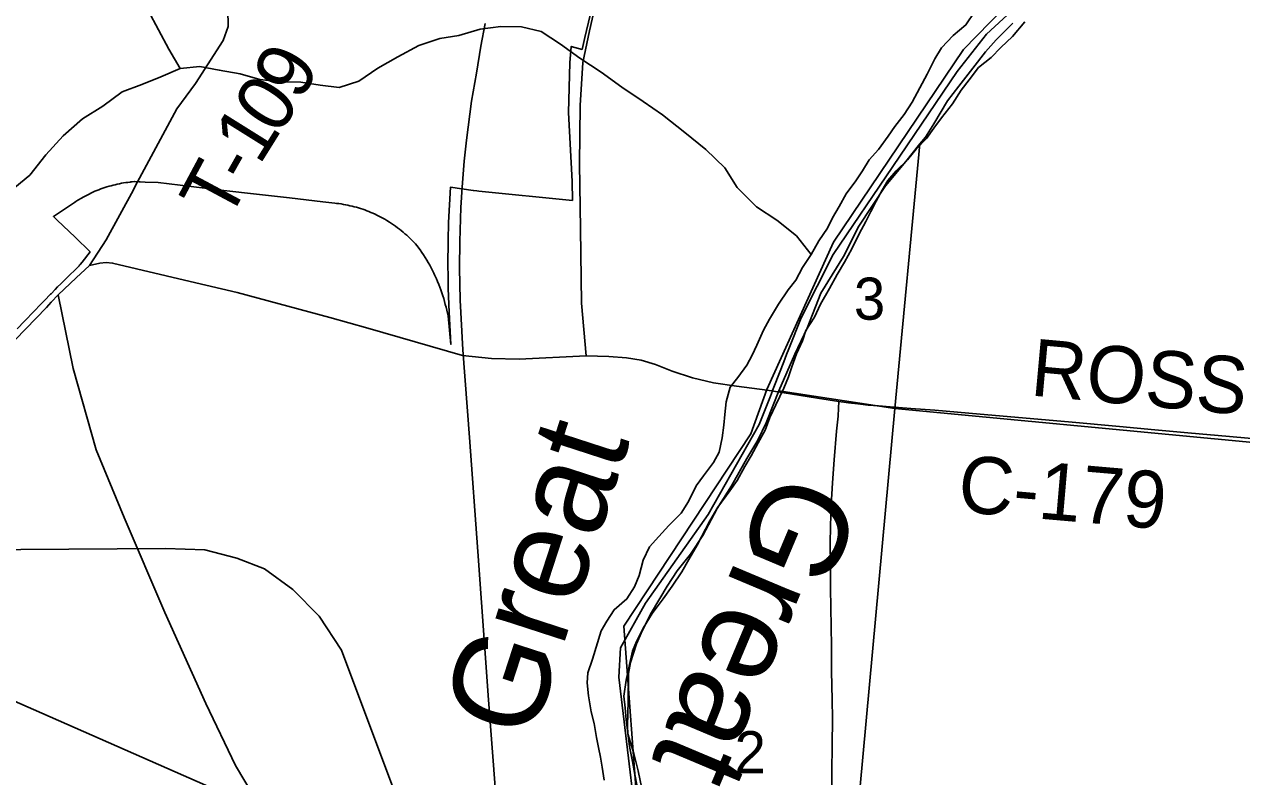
# Model space of a CAD drawing. Extents: x -38.1 to 35.9, y -2.7 to 28.5.
# Drawn here: x 9.309 to 10.521, y 16.967 to 17.716 of the extents above; entities that cross this region are included whole.
import ezdxf

# ---------------------------------------------------------------- set-up
doc = ezdxf.new("R2010")
doc.units = 0
for name, color, linetype in [('GM_X_City_Street', 7, 'Continuous'), ('GM_X_City_Street_Text', 7, 'Continuous'), ('GM_X_Corporation', 7, 'Continuous'), ('GM_X_Major_River_Text', 7, 'Continuous'), ('GM_X_Minor_Lake', 7, 'Continuous'), ('GM_X_Minor_River', 7, 'Continuous'), ('GM_X_Section', 7, 'Continuous'), ('GM_X_Township', 7, 'Continuous'), ('GM_X_Township_Road', 7, 'Continuous'), ('GM_X_Township_Road_Text', 7, 'Continuous'), ('GM_X_US_Route', 7, 'Continuous'), ('SH_Data', 7, 'Continuous')]:
    doc.layers.add(name, color=color, linetype=linetype)

msp = doc.modelspace()

# ---------------------------------------------------------------- linework, layer by layer
at = {"layer": 'GM_X_City_Street'}
for points in [[(9.8682, 17.3855), (9.8637, 17.4382), (9.8626, 17.5122), (9.8616, 17.5768), (9.8624, 17.6348), (9.8651, 17.6777), (9.8718, 17.709), (9.8893, 17.7865), (9.912, 17.8637)], [(9.6318, 16.194), (9.6477, 16.3507), (9.6404, 16.3717), (9.6476, 16.4723), (9.6557, 16.5731), (9.6614, 16.6273), (9.6602, 16.6447), (9.6546, 16.6676), (9.6322, 16.744), (9.6013, 16.8489), (9.5885, 16.8705), (9.5494, 16.9278), (9.5194, 16.9778), (9.4899, 17.0395), (9.4492, 17.1302), (9.4087, 17.2248), (9.3808, 17.2922), (9.3578, 17.3731), (9.3429, 17.4462)]]:
    msp.add_lwpolyline(points, dxfattribs=at)
at = {"layer": 'GM_X_City_Street_Text'}
msp.add_line((9.3361, 17.4389), (9.3429, 17.4462), dxfattribs=at)
for points in [[(9.3742, 17.4755), (9.3844, 17.4778), (9.3908, 17.4784), (9.3971, 17.4779), (9.4743, 17.4597), (9.5211, 17.4488), (9.6132, 17.4239), (9.6512, 17.4131), (9.7452, 17.3861), (9.7743, 17.383), (9.8018, 17.3822), (9.8682, 17.3855), (9.8909, 17.3851), (9.9085, 17.3838), (9.9232, 17.3814), (9.9372, 17.3769), (9.954, 17.3703), (9.9741, 17.3636), (9.995, 17.3588), (10.018, 17.3555), (10.0483, 17.3515)], [(9.3429, 17.4462), (9.3608, 17.4634), (9.3742, 17.4755)], [(8.9898, 17.0507), (9.0554, 17.1249), (9.1046, 17.1865), (9.1345, 17.2256), (9.1723, 17.2711), (9.2266, 17.3269), (9.3001, 17.4015), (9.3314, 17.4339), (9.3361, 17.4389)], [(10.0483, 17.3515), (10.0718, 17.3478), (10.0985, 17.3434), (10.1197, 17.3402)], [(10.1126, 16.9588), (10.1128, 16.9718), (10.1131, 16.9979), (10.1133, 17.0246), (10.113, 17.0433), (10.1124, 17.0718), (10.1124, 17.0967), (10.1113, 17.1545), (10.1114, 17.1774), (10.111, 17.1986), (10.1113, 17.2163), (10.1116, 17.2264), (10.1122, 17.2371), (10.1133, 17.2591), (10.1152, 17.2822), (10.1175, 17.3107), (10.1189, 17.3256), (10.1194, 17.3336), (10.1197, 17.3402)], [(10.1197, 17.3402), (10.1292, 17.3389), (10.1386, 17.3378), (10.1489, 17.3367), (10.1592, 17.3358), (10.1707, 17.3349), (10.1914, 17.3333), (10.2151, 17.3315), (10.2603, 17.3276), (10.3023, 17.3238), (10.3519, 17.3195), (10.3989, 17.3154), (10.4342, 17.312), (10.4669, 17.3091), (10.5085, 17.3054), (10.5492, 17.3018)]]:
    msp.add_lwpolyline(points, dxfattribs=at)
at = {"layer": 'GM_X_Corporation'}
for points in [[(9.7781, 16.9522), (9.7712, 17.0434), (9.7605, 17.191), (9.7521, 17.3043), (9.7457, 17.3917), (9.743, 17.4409), (9.7423, 17.4732), (9.7425, 17.4994), (9.7438, 17.5332), (9.7449, 17.5534), (9.747, 17.5795), (9.7493, 17.6002), (9.7544, 17.6392), (9.7591, 17.667), (9.7635, 17.6937), (9.7679, 17.7165)], [(9.925, 16.1726), (9.9171, 16.2298), (9.9036, 16.2959), (9.8921, 16.3347), (9.8349, 16.5129), (9.777, 16.6753), (9.7313, 16.799), (9.6879, 16.9246), (9.6248, 17.0926), (9.6027, 17.1264), (9.5764, 17.1531), (9.5482, 17.1735), (9.5209, 17.1843), (9.489, 17.1925), (9.4498, 17.1939), (9.2095, 17.1922)]]:
    msp.add_lwpolyline(points, dxfattribs=at)
at = {"layer": 'GM_X_Major_River_Text'}
for points in [[(9.4241, 17.5625), (9.4612, 17.6314), (9.4795, 17.6568), (9.5073, 17.6995), (9.5121, 17.7135), (9.5117, 17.7302), (9.5037, 17.782), (9.4957, 17.8212), (9.5021, 17.8666)], [(9.3742, 17.4755), (9.3907, 17.5011), (9.4179, 17.551), (9.4193, 17.5537), (9.4241, 17.5625)]]:
    msp.add_lwpolyline(points, dxfattribs=at)
at = {"layer": 'GM_X_Section'}
for points in [[(9.4645, 17.6716), (9.4531, 17.691), (9.4428, 17.71), (9.4326, 17.7294), (9.4132, 17.7522), (9.3938, 17.7663), (9.3736, 17.7803), (9.3542, 17.7959), (9.3337, 17.8081), (9.3246, 17.8302), (9.3252, 17.8588)], [(10.0923, 17.4866), (10.0775, 17.505), (10.0581, 17.5206), (10.0379, 17.5339), (10.0185, 17.5533), (10.0064, 17.5727), (9.9873, 17.5909), (9.9664, 17.608), (9.9444, 17.6255), (9.925, 17.6388), (9.9037, 17.6529), (9.8832, 17.6681), (9.8619, 17.6818), (9.8429, 17.6959), (9.8235, 17.7084), (9.8041, 17.713), (9.7835, 17.7134), (9.763, 17.7107), (9.7417, 17.7046), (9.7227, 17.7016), (9.7018, 17.6944), (9.6809, 17.6833), (9.6611, 17.6719), (9.6421, 17.659), (9.6227, 17.6526), (9.6037, 17.6549), (9.5843, 17.6579), (9.5634, 17.6583), (9.5436, 17.6606), (9.5242, 17.6663), (9.5033, 17.6701), (9.4839, 17.6735), (9.4645, 17.6716), (9.4451, 17.6632), (9.4261, 17.6557), (9.4067, 17.6484), (9.3873, 17.634), (9.3672, 17.6215), (9.3481, 17.6047), (9.3306, 17.5857), (9.3147, 17.5656), (9.2941, 17.5485)]]:
    msp.add_lwpolyline(points, dxfattribs=at)
at = {"layer": 'GM_X_Township_Road'}
for points in [[(10.2552, 17.7285), (10.2462, 17.715), (10.2335, 17.7046), (10.222, 17.6922), (10.2153, 17.6813), (10.2075, 17.6659), (10.2004, 17.6523), (10.1926, 17.638), (10.1848, 17.626), (10.1755, 17.614), (10.1689, 17.6042), (10.1592, 17.5911), (10.15, 17.5806), (10.1433, 17.5697), (10.1367, 17.5599), (10.127, 17.5468), (10.12, 17.5344), (10.1134, 17.5231), (10.1083, 17.5126), (10.0997, 17.5002), (10.0923, 17.4866), (10.0837, 17.4735), (10.0771, 17.4611), (10.0693, 17.4513), (10.0596, 17.437), (10.0507, 17.422), (10.0448, 17.4111), (10.0381, 17.3964), (10.0334, 17.3862), (10.0283, 17.3764), (10.0194, 17.364), (10.0116, 17.3543), (10.0076, 17.3399), (10.0063, 17.3274), (10.0054, 17.3168), (10.0036, 17.3039), (10.0008, 17.2899), (9.9949, 17.2794), (9.9852, 17.2663), (9.9778, 17.2561), (9.97, 17.2407), (9.963, 17.229), (9.9506, 17.2167), (9.9406, 17.2059), (9.9313, 17.1954), (9.925, 17.1822), (9.921, 17.1671), (9.9163, 17.1558), (9.9089, 17.1437), (9.8962, 17.1329), (9.8888, 17.1217), (9.8833, 17.1119), (9.8745, 17.0839), (9.8701, 17.0703), (9.8692, 17.0601), (9.8705, 17.0472), (9.8733, 17.0312), (9.8762, 17.0198), (9.8786, 17.0057), (9.8807, 16.9958), (9.8825, 16.9862), (9.8842, 16.9763), (9.8863, 16.9634)], [(10.2552, 17.7285), (10.2462, 17.715), (10.2335, 17.7046), (10.222, 17.6922), (10.2153, 17.6813), (10.2075, 17.6659), (10.2004, 17.6523), (10.1926, 17.638), (10.1848, 17.626), (10.1755, 17.614), (10.1689, 17.6042), (10.1592, 17.5911), (10.15, 17.5806), (10.1433, 17.5697), (10.1367, 17.5599), (10.127, 17.5468), (10.12, 17.5344), (10.1134, 17.5231), (10.1083, 17.5126), (10.0997, 17.5002), (10.0923, 17.4866), (10.0837, 17.4735), (10.0771, 17.4611), (10.0693, 17.4513), (10.0596, 17.437), (10.0507, 17.422), (10.0448, 17.4111), (10.0381, 17.3964), (10.0334, 17.3862), (10.0283, 17.3764), (10.0194, 17.364), (10.0116, 17.3543), (10.0076, 17.3399), (10.0063, 17.3274), (10.0054, 17.3168), (10.0036, 17.3039), (10.0008, 17.2899), (9.9949, 17.2794), (9.9852, 17.2663), (9.9778, 17.2561), (9.97, 17.2407), (9.963, 17.229), (9.9506, 17.2167), (9.9406, 17.2059), (9.9313, 17.1954), (9.925, 17.1822), (9.921, 17.1671), (9.9163, 17.1558), (9.9089, 17.1437), (9.8962, 17.1329), (9.8888, 17.1217), (9.8833, 17.1119), (9.8745, 17.0839), (9.8701, 17.0703), (9.8692, 17.0601), (9.8705, 17.0472), (9.8733, 17.0312), (9.8762, 17.0198), (9.8786, 17.0057), (9.8807, 16.9958), (9.8825, 16.9862), (9.8842, 16.9763), (9.8863, 16.9634)], [(9.9189, 16.9587), (9.9168, 16.969), (9.9143, 16.9819), (9.9115, 16.9968), (9.9098, 17.0105), (9.9081, 17.0234), (9.9072, 17.0352), (9.9058, 17.047), (9.908, 17.0629), (9.9116, 17.0784), (9.9145, 17.0916), (9.9185, 17.1014), (9.9251, 17.1146), (9.9341, 17.1293), (9.9449, 17.1439), (9.9539, 17.1563), (9.9636, 17.1706), (9.9706, 17.183), (9.9788, 17.1973), (9.9913, 17.2214), (9.9995, 17.2349), (10.0112, 17.2514), (10.0185, 17.2615), (10.0263, 17.2755), (10.0326, 17.286), (10.0396, 17.2992), (10.0463, 17.3116), (10.051, 17.3244), (10.0569, 17.3369), (10.0651, 17.3534), (10.0695, 17.3647), (10.0731, 17.3746), (10.0775, 17.3878), (10.0837, 17.4006), (10.0869, 17.4108), (10.0955, 17.4243), (10.1014, 17.4371), (10.1104, 17.4525), (10.1182, 17.4665), (10.1252, 17.4789), (10.1326, 17.492), (10.1401, 17.5071), (10.1467, 17.5192), (10.1514, 17.5293), (10.1569, 17.5395), (10.1628, 17.5504), (10.1686, 17.5602), (10.1767, 17.5699), (10.1879, 17.5808), (10.1968, 17.5913), (10.2069, 17.6021), (10.2142, 17.6122), (10.222, 17.6224), (10.2328, 17.6366), (10.2414, 17.6501), (10.2495, 17.6603), (10.2588, 17.6726), (10.2712, 17.6827), (10.2808, 17.6924), (10.2924, 17.7036), (10.3047, 17.7182)], [(9.9189, 16.9587), (9.9168, 16.969), (9.9143, 16.9819), (9.9115, 16.9968), (9.9098, 17.0105), (9.9081, 17.0234), (9.9072, 17.0352), (9.9058, 17.047), (9.908, 17.0629), (9.9116, 17.0784), (9.9145, 17.0916), (9.9185, 17.1014), (9.9251, 17.1146), (9.9341, 17.1293), (9.9449, 17.1439), (9.9539, 17.1563), (9.9636, 17.1706), (9.9706, 17.183), (9.9788, 17.1973), (9.9913, 17.2214), (9.9995, 17.2349), (10.0112, 17.2514), (10.0185, 17.2615), (10.0263, 17.2755), (10.0326, 17.286), (10.0396, 17.2992), (10.0463, 17.3116), (10.051, 17.3244), (10.0569, 17.3369), (10.0651, 17.3534), (10.0695, 17.3647), (10.0731, 17.3746), (10.0775, 17.3878), (10.0837, 17.4006), (10.0869, 17.4108), (10.0955, 17.4243), (10.1014, 17.4371), (10.1104, 17.4525), (10.1182, 17.4665), (10.1252, 17.4789), (10.1326, 17.492), (10.1401, 17.5071), (10.1467, 17.5192), (10.1514, 17.5293), (10.1569, 17.5395), (10.1628, 17.5504), (10.1686, 17.5602), (10.1767, 17.5699), (10.1879, 17.5808), (10.1968, 17.5913), (10.2069, 17.6021), (10.2142, 17.6122), (10.222, 17.6224), (10.2328, 17.6366), (10.2414, 17.6501), (10.2495, 17.6603), (10.2588, 17.6726), (10.2712, 17.6827), (10.2808, 17.6924), (10.2924, 17.7036), (10.3047, 17.7182)]]:
    msp.add_lwpolyline(points, dxfattribs=at)
at = {"layer": 'GM_X_US_Route'}
for points in [[(11.2671, 18.2524), (11.175, 17.2383), (10.1754, 17.3332), (10.2004, 17.5967), (10.2059, 17.6034), (10.2144, 17.6165), (10.2277, 17.6393), (10.239, 17.6539), (10.253, 17.6718), (10.2658, 17.6882), (10.2762, 17.7002), (10.2928, 17.7169)], [(9.9048, 17.861), (9.867, 17.7024), (9.8642, 17.6907), (9.8535, 17.6936), (9.8522, 17.6773), (9.8509, 17.6277), (9.8545, 17.559), (9.8547, 17.5404), (9.7615, 17.5497), (9.7597, 17.5499), (9.7564, 17.5503), (9.7559, 17.5503), (9.7333, 17.5534), (9.7322, 17.5358), (9.7314, 17.5182), (9.731, 17.5006), (9.7308, 17.4757), (9.731, 17.4648), (9.7312, 17.4525), (9.732, 17.4292), (9.7338, 17.397), (9.7309, 17.4253), (9.7303, 17.4282), (9.7297, 17.4311), (9.729, 17.434), (9.7282, 17.4369), (9.7274, 17.4398), (9.7266, 17.4427), (9.7257, 17.4455), (9.7248, 17.4484), (9.7238, 17.4512), (9.7227, 17.454), (9.7216, 17.4568), (9.7205, 17.4596), (9.7193, 17.4623), (9.7181, 17.4651), (9.7174, 17.4664), (9.7168, 17.4678), (9.7155, 17.4705), (9.7141, 17.4731), (9.7127, 17.4758), (9.7112, 17.4784), (9.7097, 17.481), (9.7081, 17.4835), (9.7065, 17.4861), (9.7049, 17.4886), (9.7032, 17.491), (9.7, 17.4955), (9.6984, 17.4972), (9.6967, 17.499), (9.695, 17.5007), (9.6933, 17.5024), (9.6916, 17.504), (9.6898, 17.5056), (9.688, 17.5072), (9.6862, 17.5088), (9.6843, 17.5103), (9.6825, 17.5118), (9.6806, 17.5132), (9.6786, 17.5146), (9.6767, 17.516), (9.6747, 17.5174), (9.6727, 17.5187), (9.67, 17.5205), (9.668, 17.5216), (9.6661, 17.5226), (9.6642, 17.5237), (9.6622, 17.5247), (9.6602, 17.5257), (9.6583, 17.5266), (9.6562, 17.5275), (9.6542, 17.5284), (9.6522, 17.5292), (9.6501, 17.53), (9.6481, 17.5308), (9.646, 17.5315), (9.6439, 17.5322), (9.6418, 17.5329), (9.6397, 17.5335), (9.6375, 17.5341), (9.6354, 17.5346), (9.6333, 17.5351), (9.6311, 17.5356), (9.629, 17.536), (9.6268, 17.5364), (9.6246, 17.5368), (9.6224, 17.5371), (9.62, 17.5374), (9.6182, 17.5376), (9.6063, 17.539), (9.5732, 17.5428), (9.5405, 17.5465), (9.5078, 17.5502), (9.4752, 17.5542), (9.4425, 17.5582), (9.4296, 17.5586), (9.4245, 17.5588), (9.4242, 17.5588), (9.4236, 17.5588), (9.4188, 17.559), (9.4187, 17.559), (9.4166, 17.5588), (9.4154, 17.5587), (9.4145, 17.5586), (9.4124, 17.5583), (9.4103, 17.558), (9.4081, 17.5577), (9.406, 17.5574), (9.4039, 17.557), (9.4018, 17.5565), (9.3998, 17.556), (9.3977, 17.5555), (9.3956, 17.555), (9.3936, 17.5544), (9.3915, 17.5538), (9.3895, 17.5531), (9.3875, 17.5525), (9.3855, 17.5517), (9.3835, 17.551), (9.3815, 17.5502), (9.3795, 17.5494), (9.3775, 17.5485), (9.3756, 17.5476), (9.3737, 17.5467), (9.3718, 17.5457), (9.3699, 17.5447), (9.368, 17.5437), (9.3662, 17.5426), (9.3627, 17.5405), (9.3606, 17.5392), (9.3592, 17.5383), (9.3383, 17.5243), (9.342, 17.5208), (9.3598, 17.5036), (9.3748, 17.4892), (9.367, 17.479), (9.365, 17.4766), (9.3643, 17.4758), (9.3638, 17.4752), (9.3631, 17.4745), (9.3622, 17.4736), (9.3612, 17.4725), (9.3598, 17.4712), (9.3542, 17.4658), (9.3508, 17.4624), (9.3507, 17.4623), (9.3477, 17.4594), (9.3457, 17.4574), (9.3425, 17.4542), (9.3399, 17.4516), (9.3359, 17.4472), (9.3355, 17.4469), (9.3295, 17.4407), (9.3239, 17.435), (9.3209, 17.4319), (9.3192, 17.4301), (9.3096, 17.4202), (9.3021, 17.4126)], [(10.5289, 15.2826), (10.371, 15.2977), (10.3693, 15.4805), (10.2951, 15.5761), (10.189, 15.7709), (10.0943, 15.8677), (10.049, 15.963), (10.0159, 16.0586), (10.0182, 16.2504), (9.9816, 16.4421), (9.9421, 16.829), (9.92, 16.9247), (9.9059, 17.1165), (10.0322, 17.3079), (10.0481, 17.3521), (10.1143, 17.4989), (10.2437, 17.6904), (10.3361, 17.7853)], [(10.3361, 17.7853), (10.2437, 17.6904), (10.1143, 17.4989), (10.0481, 17.3521), (10.0322, 17.3079), (9.9059, 17.1165), (9.92, 16.9247), (9.9421, 16.829), (9.9816, 16.4421), (10.0182, 16.2504), (10.0159, 16.0586), (10.049, 15.963), (10.0943, 15.8677), (10.189, 15.7709), (10.2951, 15.5761), (10.3693, 15.4805), (10.371, 15.2977), (10.5289, 15.2826)], [(10.3774, 15.25), (10.371, 15.2977), (10.3693, 15.4805), (10.2951, 15.5761), (10.189, 15.7709), (10.0943, 15.8677), (10.049, 15.963), (10.0159, 16.0586), (10.0182, 16.2504), (9.9816, 16.4421), (9.9421, 16.829), (9.92, 16.9247), (9.9059, 17.1165), (10.0322, 17.3079), (10.0481, 17.3521), (10.1143, 17.4989), (10.2437, 17.6904), (10.3361, 17.7853)], [(10.3361, 17.7853), (10.2437, 17.6904), (10.1143, 17.4989), (10.0481, 17.3521), (10.0322, 17.3079), (9.9059, 17.1165), (9.92, 16.9247), (9.9421, 16.829), (9.9816, 16.4421), (10.0182, 16.2504), (10.0159, 16.0586), (10.049, 15.963), (10.0943, 15.8677), (10.189, 15.7709), (10.2951, 15.5761), (10.3693, 15.4805), (10.371, 15.2977), (10.5289, 15.2826)], [(9.9252, 16.8629), (9.9007, 17.0659), (9.9026, 17.0949), (9.9275, 17.1395), (9.9898, 17.2278), (10.0406, 17.3174), (10.0516, 17.3454), (10.0537, 17.3509), (10.0538, 17.3511), (10.0558, 17.3562), (10.065, 17.3798), (10.0678, 17.387), (10.07, 17.3926), (10.0821, 17.4235), (10.114, 17.4864), (10.1734, 17.5741), (10.2373, 17.6687), (10.2665, 17.7058), (10.3248, 17.7595)], [(9.9237, 16.955), (9.9202, 16.9725), (9.9156, 16.99), (9.9099, 17.0094), (9.9093, 17.0174), (9.9102, 17.042), (9.9103, 17.0696), (9.9124, 17.0805), (9.9184, 17.099), (9.9244, 17.1125), (9.9334, 17.1301), (9.949, 17.1564), (9.9588, 17.1717), (9.972, 17.1881), (9.9845, 17.2068), (9.9986, 17.2338), (10.013, 17.2563), (10.0283, 17.2836), (10.0393, 17.3016), (10.0475, 17.3189), (10.0599, 17.3509), (10.1754, 17.3332), (10.0836, 16.332)]]:
    msp.add_lwpolyline(points, dxfattribs=at)
for points in [[(10.0599, 17.3509), (10.0759, 17.3872), (10.0883, 17.4132), (10.1019, 17.448), (10.1243, 17.4846), (10.1396, 17.5147), (10.1662, 17.5548), (10.1863, 17.579), (10.2004, 17.5967), (10.1754, 17.3332)], [(10.1754, 17.3332), (11.175, 17.2383), (11.0788, 16.2278), (10.0836, 16.332)]]:
    msp.add_lwpolyline(points, close=True, dxfattribs=at)
at = {"layer": 'SH_Data'}
msp.add_lwpolyline([(7.839, 17.3766), (11.5732, 16.0414), (7.839, 17.6847)], close=True, dxfattribs=at)

# ---------------------------------------------------------------- texts
at = {"layer": 'GM_X_Minor_Lake'}
for s, rotation, p in [('9', 61.4979, (9.5841, 17.6378)), ('0', 55.9058, (9.5614, 17.6037)), ('1', 57.9554, (9.5431, 17.5744)), ('-', 60.442, (9.5319, 17.5547)), ('T', 61.8574, (9.512, 17.5175))]:
    msp.add_text(s, height=0.0568, rotation=rotation, dxfattribs=at).set_placement(p)
at = {"layer": 'GM_X_Minor_River'}
for s, p in [('3', (10.1347, 17.4216)), ('2', (10.016, 16.9702))]:
    msp.add_text(s, height=0.0419, rotation=0, dxfattribs=at).set_placement(p)
at = {"layer": 'GM_X_Township'}
for s, rotation, p in [('ROSS', 354.7755, (10.3093, 17.3463)), ('C-179', 355.0537, (10.2369, 17.2307))]:
    msp.add_text(s, height=0.05682, rotation=rotation, dxfattribs=at).set_placement(p)
at = {"layer": 'GM_X_Township_Road_Text'}
for rotation, p in [(72, (9.8141, 17.0002)), (247.1803, (10.056, 17.2754))]:
    msp.add_text('Great', height=0.09469, rotation=rotation, dxfattribs=at).set_placement(p)

doc.saveas('drawing.dxf')
